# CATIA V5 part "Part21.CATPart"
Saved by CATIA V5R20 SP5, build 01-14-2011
Part number: Part21
Material "Water": density 1000 kg/m3
Bounding box of the stored display mesh (mm): x -1.919 to 1.919, y -2 to 2, z -1.919 to 1.919
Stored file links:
  D:\新建文件夹\Part21.CATPart
  C:\Program Files\Dassault Systemes\B20\intel_a\startup\materials\Catalog.CATMaterial
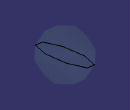
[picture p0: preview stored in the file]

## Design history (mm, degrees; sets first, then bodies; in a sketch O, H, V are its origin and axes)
Body1 (main body), material "Water"
  Sketch1 on xy-plane, origin (0, 0, 0), H (1, 0, 0), V (0, 1, 0)
    arc A1 centre (0, 0) radius 2 from (0, -2) to (0, 2) ccw
    axis line L1 (0, 5.9256) -> (0, -6.5373)
    point P1 (0, 5.9256)
    point P3 (0, 2)
    point P4 (0, -2)
    radius A1 = 2
    coincidence: P1 V, L1 P3, L1 P4
    vertical: L1 V
  Shaft1: profile Sketch1, axis Sketch1.L1, angle 360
